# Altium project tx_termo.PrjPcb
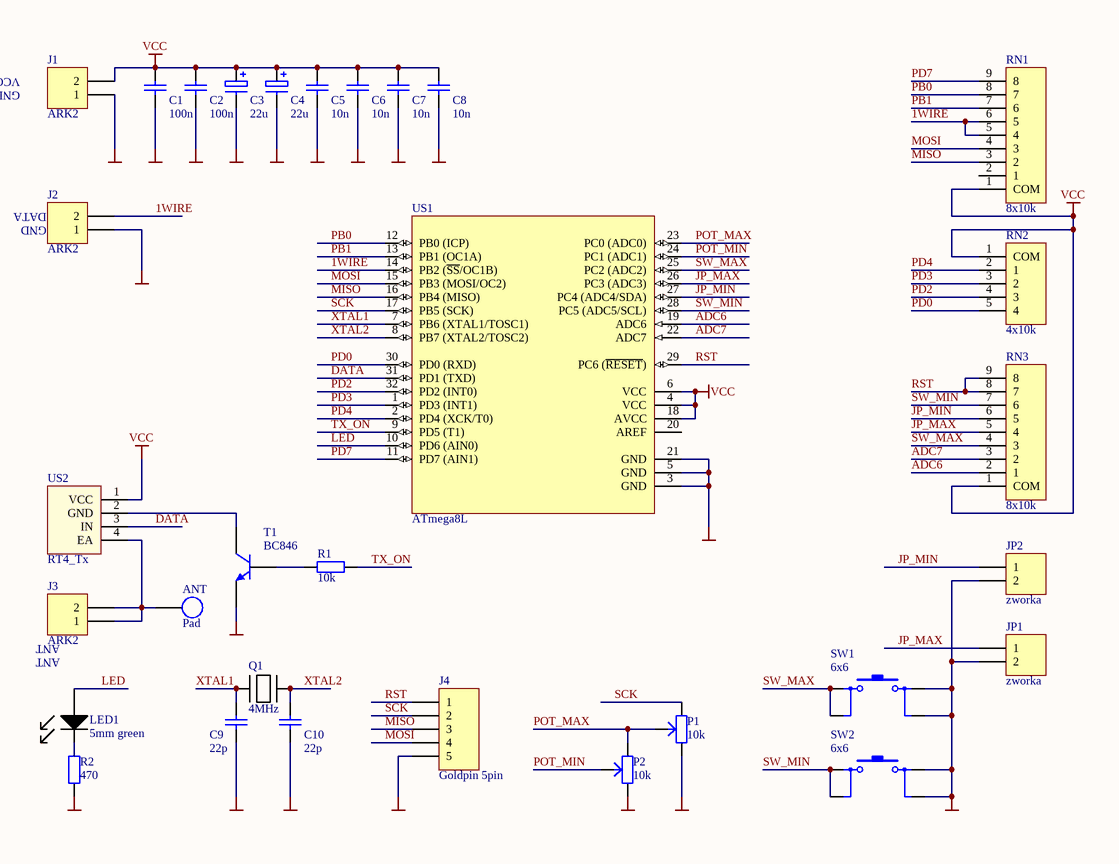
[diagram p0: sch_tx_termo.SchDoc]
1 sheet, 31 parts. Net scope: global (net labels, ports and power ports of the same name join across sheets).
Board file: pcb_tx_termo.PcbDoc

## Sheet sch_tx_termo.SchDoc
size A4

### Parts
ANT  Pad  [Pad SMD 2x4mm]
C1  100n  [MELF-1206]
C2  100n  [MELF-1206]
C3  22u  [2,5/5mm elektrolit]
C4  22u  [2,5/5mm elektrolit]
C5  10n  [MELF-1206]
C6  10n  [MELF-1206]
C7  10n  [MELF-1206]
C8  10n  [MELF-1206]
C9  22p  [MELF-1206]
C10  22p  [MELF-1206]
J1  ARK2  [ARK2 3,5mm]
J2  ARK2  [ARK2 3,5mm]
J3  ARK2  [ARK2 3,5mm]
J4  Goldpin 5pin  [HDR1X5]
JP1  zworka  [HDR1X2]
JP2  zworka  [HDR1X2]
LED1  5mm green  [LED 5mm]
P1  10k  [pot mont poziom]
P2  10k  [pot mont poziom]
Q1  4MHz  [kwarc 5mm]
R1  10k  [MELF-1206]
R2  470  [MELF-1206]
RN1  8x10k  [SIL9]
RN2  4x10k  [SIL5]
RN3  8x10k  [SIL9]
SW1  6x6  [tact switch 6x6]
SW2  6x6  [tact switch 6x6]
T1  BC846  [318-08]
US1  ATmega8L  [32A_N]
US2  RT4_Tx  [RT4_Tx]

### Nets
GND: C1.1 C2.1 C3.2 C4.2 C5.1 C6.1 C7.1 C8.1 C9.2 C10.2 J1.1 J2.1 J4.5 JP1.2 JP2.2 P1.a P2.a R2.1 SW1.2 SW1.4 SW2.2 SW2.4 T1.2(E) US1.3(GND) US1.5(GND) US1.21(GND)
VCC: C1.2 C2.2 C3.1 C4.1 C5.2 C6.2 C7.2 C8.2 J1.2 RN1.1(COM) RN2.1(COM) RN3.1(COM) US1.4(VCC) US1.6(VCC) US1.18(AVCC) US2.1(VCC)
1WIRE: J2.2 RN1.5(4) RN1.6(5) US1.14(PB2_(~{SS}/OC1B))
ADC6: RN3.2(1) US1.19(ADC6)
ADC7: RN3.3(2) US1.22(ADC7)
DATA: US1.31(PD1_(TXD)) US2.3(IN)
JP_MAX: JP1.1 RN3.5(4) US1.26(PC3_(ADC3))
JP_MIN: JP2.1 RN3.6(5) US1.27(PC4_(ADC4/SDA))
LED: LED1.A US1.10(PD6_(AIN0))
MISO: J4.3 RN1.3(2) US1.16(PB4_(MISO))
MOSI: J4.4 RN1.4(3) US1.15(PB3_(MOSI/OC2))
PB0: RN1.8(7) US1.12(PB0_(ICP))
PB1: RN1.7(6) US1.13(PB1_(OC1A))
PD0: RN2.5(4) US1.30(PD0_(RXD))
PD2: RN2.4(3) US1.32(PD2_(INT0))
PD3: RN2.3(2) US1.1(PD3_(INT1))
PD4: RN2.2(1) US1.2(PD4_(XCK/T0))
PD7: RN1.9(8) US1.11(PD7_(AIN1))
POT_MAX: P1.c P2.b US1.23(PC0_(ADC0))
POT_MIN: P2.c US1.24(PC1_(ADC1))
RST: J4.1 RN3.8(7) RN3.9(8) US1.29(PC6_(~{RESET}))
SCK: J4.2 P1.b US1.17(PB5_(SCK))
SW_MAX: RN3.4(3) SW1.1 SW1.3 US1.25(PC2_(ADC2))
SW_MIN: RN3.7(6) SW2.1 SW2.3 US1.28(PC5_(ADC5/SCL))
TX_ON: R1.2 US1.9(PD5_(T1))
XTAL1: C9.1 Q1.1 US1.7(PB6_(XTAL1/TOSC1))
XTAL2: C10.1 Q1.2 US1.8(PB7_(XTAL2/TOSC2))
NetANT_1: ANT.1 J3.1 J3.2 US2.4(EA)
NetLED1_K: LED1.K R2.2
NetR1_1: R1.1 T1.1(B)
NetT1_3: T1.3(C) US2.2(GND)

Not connected (* = marked no-connect by the designer): RN1 2(1); US1 20(AREF)

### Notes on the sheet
- VCC
- GND
- (near J2) DATA
- (near J2) GND
- ANT
- (near J3) ANT

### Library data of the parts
C1 C2 C5-C10 = kondensator
C3 C4 = kond biegunowy: Polarized Capacitor
J4 = Header 5: Header, 5-Pin
JP1 JP2 = Header 2: Header, 2-Pin
LED1 = LED
P1 P2 = pot mont
Q1 = kwarc
R1 R2 = rezystor
RN1 RN3 = drab rez x 8: Header, 9-Pin
RN2 = drab rez x 4
SW1 SW2 = switch
T1 = BC846ALT1: General Purpose Transistor NPN Silicon
US1 = ATmega8L-8AI: 8-Bit AVR Microcontroller with 8K Bytes of In-System Programmable Flash Memory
